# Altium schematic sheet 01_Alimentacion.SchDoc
size A; SheetNumber: 1; SheetTotal: 4
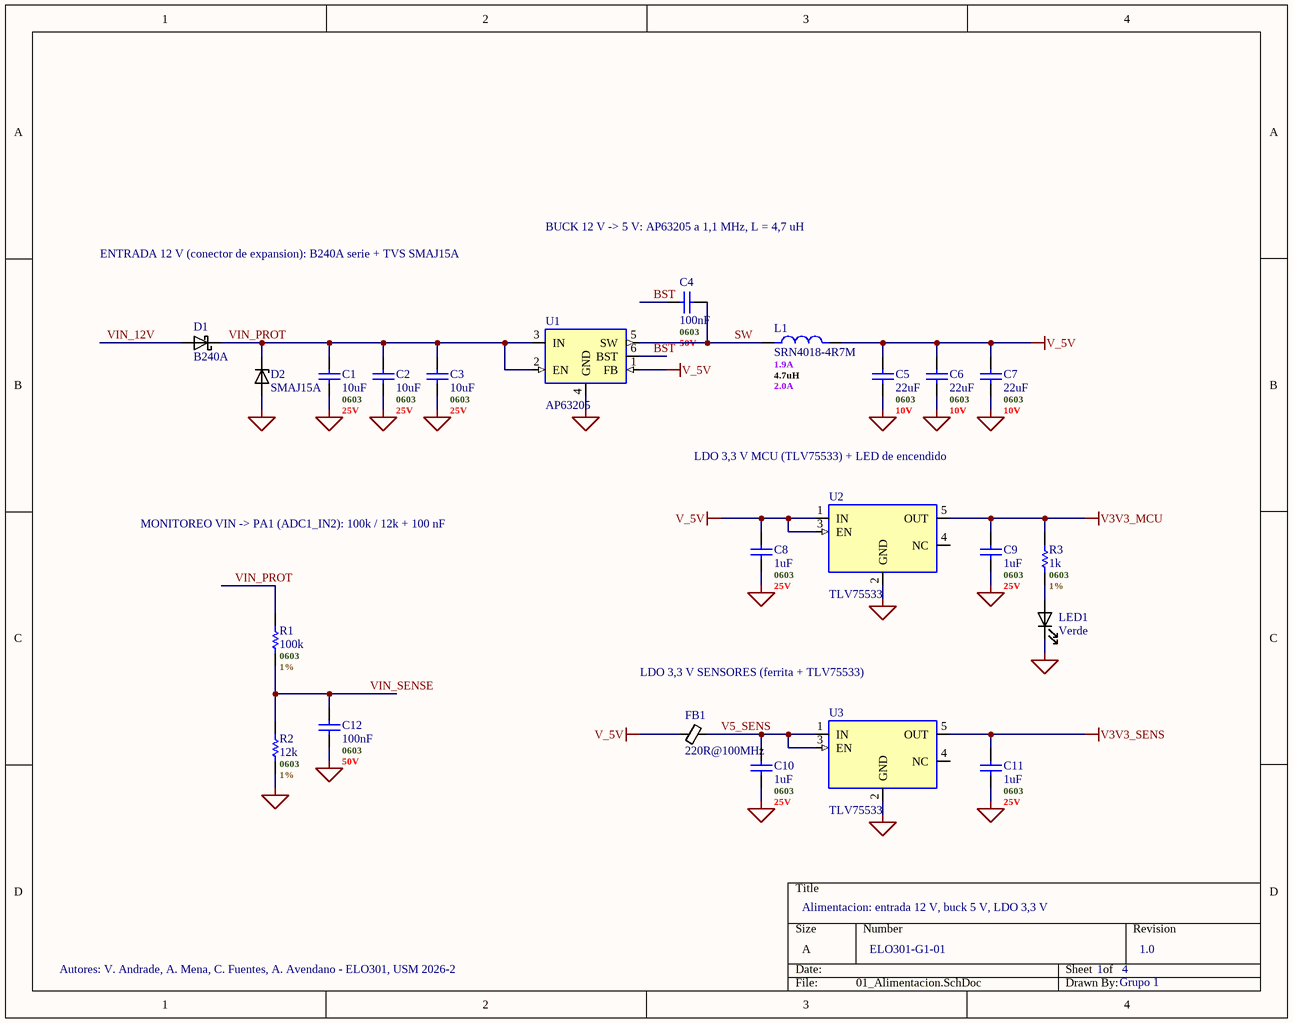
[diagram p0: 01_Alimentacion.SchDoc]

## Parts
C1  10uF  .Case/Package: 0603  .Voltage Rating (DC): 25V  [C0603 - MURATA]
C2  10uF  .Case/Package: 0603  .Voltage Rating (DC): 25V  [C0603 - MURATA]
C3  10uF  .Case/Package: 0603  .Voltage Rating (DC): 25V  [C0603 - MURATA]
C4  100nF  .Case/Package: 0603  .Voltage Rating (DC): 50V  [C0603 - MURATA]
C5  22uF  .Case/Package: 0603  .Voltage Rating (DC): 10V  [C0603 - MURATA]
C6  22uF  .Case/Package: 0603  .Voltage Rating (DC): 10V  [C0603 - MURATA]
C7  22uF  .Case/Package: 0603  .Voltage Rating (DC): 10V  [C0603 - MURATA]
C8  1uF  .Case/Package: 0603  .Voltage Rating (DC): 25V  [C0603 - MURATA]
C9  1uF  .Case/Package: 0603  .Voltage Rating (DC): 25V  [C0603 - MURATA]
C10  1uF  .Case/Package: 0603  .Voltage Rating (DC): 25V  [C0603 - MURATA]
C11  1uF  .Case/Package: 0603  .Voltage Rating (DC): 25V  [C0603 - MURATA]
C12  100nF  .Case/Package: 0603  .Voltage Rating (DC): 50V  [C0603 - MURATA]
D1  B240A  [SMA - DIODES]
D2  SMAJ15A  [SMA - DIODES]
FB1  220R@100MHz  [L0603 - GENERIC]
L1  SRN4018-4R7M  .RMS Current (Irms): 1.9A  .Value: 4.7uH  .Max DC Current: 2.0A  [SRN4018 - BOURNS]
LED1  Verde  [LED0603 - LITEON]
R1  100k  .Case/Package: 0603  .Tolerance: 1%  [R0603 - YAGEO]
R2  12k  .Case/Package: 0603  .Tolerance: 1%  [R0603 - YAGEO]
R3  1k  .Case/Package: 0603  .Tolerance: 1%  [R0603 - YAGEO]
U1  AP63205  [TSOT-23-6 - DIODES]
U2  TLV75533  [SOT-23-5 - TI]
U3  TLV75533  [SOT-23-5 - TI]

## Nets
GND: C1.2 C2.2 C3.2 C5.2 C6.2 C7.2 C8.2 C9.2 C10.2 C11.2 C12.2 D2.2(A) LED1.1(K) R2.1 U1.4(GND) U2.2(GND) U3.2(GND)
V3V3_MCU: C9.1 R3.2 U2.5(OUT)
V3V3_SENS: C11.1 U3.5(OUT)
V_5V: C5.1 C6.1 C7.1 C8.1 FB1.1 L1.2 U1.1(FB) U2.1(IN) U2.3(EN)
BST: C4.1 U1.6(BST)
SW: C4.2 L1.1 U1.5(SW)
V5_SENS: C10.1 FB1.2 U3.1(IN) U3.3(EN)
VIN_12V: D1.2(A)
VIN_PROT: C1.1 C2.1 C3.1 D1.1(K) D2.1(K) R1.2 U1.2(EN) U1.3(IN)
VIN_SENSE: C12.1 R1.1 R2.2
NetLED1_2: LED1.2(A) R3.1

Not connected (* = marked no-connect by the designer): U2 4(NC); U3 4(NC)

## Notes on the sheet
- BUCK 12 V -> 5 V: AP63205 a 1,1 MHz, L = 4,7 uH
- ENTRADA 12 V (conector de expansion): B240A serie + TVS SMAJ15A
- LDO 3,3 V MCU (TLV75533) + LED de encendido
- MONITOREO VIN -> PA1 (ADC1_IN2): 100k / 12k + 100 nF
- LDO 3,3 V SENSORES (ferrita + TLV75533)
- Alimentacion: entrada 12 V, buck 5 V, LDO 3,3 V
- Autores: V. Andrade, A. Mena, C. Fuentes, A. Avendano - ELO301, USM 2026-2
- ELO301-G1-01
- 1
- 4
- 1.0
- Grupo 1

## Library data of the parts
C1-C3 = CAP - GENERIC: Manufacturer: Murata; Manufacturer Part Number: GRM188R61E106MA73D
C4 C12 = CAP - GENERIC: Manufacturer: Murata; Manufacturer Part Number: GRM188R71H104KA93D
C5-C7 = CAP - GENERIC: Manufacturer: Murata; Manufacturer Part Number: GRM188R61A226ME15D
C8-C11 = CAP - GENERIC: Manufacturer: Murata; Manufacturer Part Number: GRM188R61E105KA12D
D1 = B240A-13-F: Schottky diode; Manufacturer: Diodes Inc.
D2 = SMAJ15A-13-F: Diodes SMAJ15A TVS unidireccional 400 W, 15 V de trabajo, SMA; Manufacturer: Diodes Inc.
FB1 = FERRITE - GENERIC: Ferrite bead, small symbol; Manufacturer: Murata; Manufacturer Part Number: BLM18PG221SN1D
L1 = INDUCTOR - GENERIC: Manufacturer: Bourns; Value: 4.7uH
LED1 = LED - GENERIC: Light emitting diode; Manufacturer: Lite-On; Manufacturer Part Number: LTST-C191KGKT
R1 = RESISTOR - GENERIC: Manufacturer: Yageo; Manufacturer Part Number: RC0603FR-07100KL
R2 = RESISTOR - GENERIC: Manufacturer: Yageo; Manufacturer Part Number: RC0603FR-0712KL
R3 = RESISTOR - GENERIC: Manufacturer: Yageo; Manufacturer Part Number: RC0603FR-071KL
U1 = AP63205WU-7: 2A, 1.1MHz Buck DC/DC Converter, fixed 5.0V output voltage, TSOT-23-6; Manufacturer: Diodes Inc.
U2 U3 = TLV75533PDBVR: TI TLV75533 LDO 500 mA, salida fija 3,3 V, SOT-23-5; Manufacturer: Texas Instruments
